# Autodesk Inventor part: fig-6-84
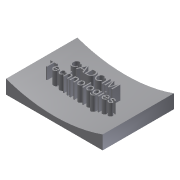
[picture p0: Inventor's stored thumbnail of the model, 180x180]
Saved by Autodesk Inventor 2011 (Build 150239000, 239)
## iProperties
Shininess: 64.0
Length Units: 11269
Angle Units: 11279
Time Units: 11290
Mass Units: 11283
Length Display Precision: 3
Angle Display Precision: 2
Compacted: True
Part Number: fig-6-84
Document SubType Name: Modeling
Created: 2002-12
Designer: deepak
Density: 1 g/cm^3
Density: 0.0
Volumn: 0.0
Area: 0.0
PropertySet Name: Model Information
Control State: 0
Master: False
Checked Out: False
Author: deepak
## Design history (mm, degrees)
sketch "Sketch1"
  geometry: L1 (-39.922, 33.786)-(30.103, 33.786); L2 (30.103, 33.786)-(30.103, -17.894); L3 (30.103, -17.894)-(-39.922, -17.894); L4 (-39.922, -17.894)-(-39.922, 33.786)
  constraints: 8 end point, 2 parallel, 1 horizontal, 1 perpendicular
extrude "Extrusion1" new body sketch "Sketch1" distance "d0" = 10; taper "d1" = 0 deg
workplane "Work Plane1"
sketch "Sketch2"
  geometry: L1 (-37.656, 15.034)-(26.28, 15.034); L2 (26.28, 15.034)-(26.28, 10.168); L3 (26.28, 10.168)-(-37.656, 10.168); L4 (-37.656, 10.168)-(-37.656, 15.034)
  constraints: 2 other
sketch "Sketch3"
  geometry: L1 (70.026, 10)-(0, 10) reference; A1 r 105 centre (35.013, 108.99) between (0, 10) and (70.026, 10)
  constraints: 2 point on circle, 1 centre point
  dimensions: "d5" = 105 radius of A1
extrude "Extrusion2" cut sketch "Sketch3" stored distance "d3" = 10; taper "d4" = 0 deg
emboss "Emboss4" sketch "Sketch2" dims "d14" = 1, "d15" = 0
body "Solid1"
other parameters: "d2" = 5
